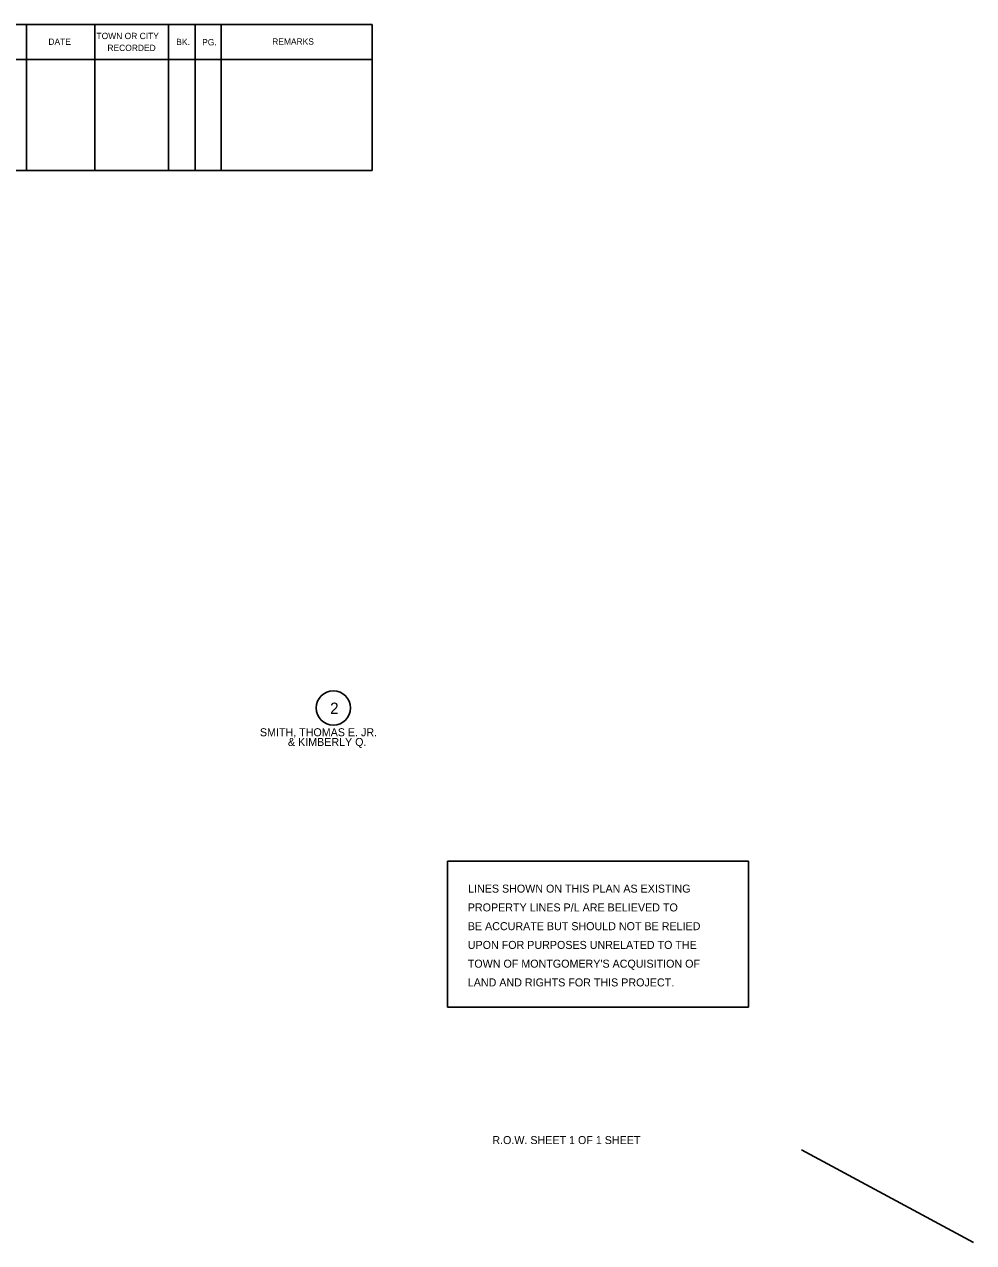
# Model space of a CAD drawing. Extents: x 10908 to 11683, y 59533 to 60252.
# Drawn here: x 11350.8 to 11682.8, y 59532.8 to 59959.1 of the extents above; entities that cross this region are included whole.
import ezdxf

# ---------------------------------------------------------------- set-up
doc = ezdxf.new("R2010")
doc.units = 0
for name, color, linetype in [('Level 1', 7, 'Continuous'), ('Level 4', 7, 'Continuous'), ('Level 5', 7, 'Continuous')]:
    doc.layers.add(name, color=color, linetype=linetype)

msp = doc.modelspace()

# ---------------------------------------------------------------- linework, layer by layer
at = {"layer": 'Level 1'}
for p, q in [((11047.77, 59959.1), (11472.37, 59959.1)), ((11351.56, 59959.01), (11351.56, 59907.92)), ((11375.36, 59907.92), (11375.36, 59959.1)), ((11401.19, 59907.92), (11401.19, 59958.93)), ((11410.46, 59907.92), (11410.46, 59959.1)), ((11419.55, 59907.92), (11419.55, 59959.1)), ((11472.37, 59959.1), (11472.37, 59907.92)), ((11047.77, 59946.84), (11472.37, 59946.84)), ((11047.77, 59907.92), (11472.37, 59907.92)), ((11498.77, 59666.27), (11604.06, 59666.27)), ((11498.77, 59666.27), (11498.78, 59615.28)), ((11604.06, 59666.27), (11604.06, 59615.28)), ((11498.78, 59615.28), (11604.06, 59615.28)), ((11622.59, 59565.36), (11682.76, 59532.84))]:
    msp.add_line(p, q, dxfattribs=at)
at = {"layer": 'Level 5'}
msp.add_circle((11458.84, 59719.92), 6, dxfattribs=at)

# ---------------------------------------------------------------- texts
at = {"layer": 'Level 1'}
for s, height, p in [('DATE', 2.207, (11359.17, 59951.94)), ('TOWN OR CITY', 2.2074, (11375.99, 59953.94)), ('BK.', 2.207, (11403.91, 59951.85)), ('PG.', 2.207, (11412.94, 59951.75)), ('REMARKS', 2.207, (11437.44, 59951.98)), ('RECORDED', 2.207, (11379.81, 59949.77)), ('LINES SHOWN ON THIS PLAN AS EXISTING', 2.8, (11505.95, 59655.31)), ('BE ACCURATE BUT SHOULD NOT BE RELIED', 2.8, (11505.85, 59642.17)), ('UPON FOR PURPOSES UNRELATED TO THE', 2.8, (11505.85, 59635.61)), ("TOWN OF MONTGOMERY'S ACQUISITION OF ", 2.8, (11505.85, 59629.05)), ('LAND AND RIGHTS FOR THIS PROJECT.', 2.8, (11505.85, 59622.49)), ('R.O.W. SHEET 1 OF 1 SHEET', 2.8, (11514.43, 59567.33))]:
    msp.add_text(s, height=height, dxfattribs=at).set_placement(p)
msp.add_text('PROPERTY LINES P/L ARE BELIEVED TO', height=2.8, rotation=0.0007, dxfattribs=at).set_placement((11505.85, 59648.73))
at = {"layer": 'Level 4'}
for s, p in [('SMITH, THOMAS E. JR.', (11433.14, 59710.02)), ('& KIMBERLY Q.', (11442.94, 59706.62))]:
    msp.add_text(s, height=2.8, dxfattribs=at).set_placement(p)
at = {"layer": 'Level 5'}
msp.add_text('2', height=4, dxfattribs=at).set_placement((11457.68, 59717.79))

doc.saveas('drawing.dxf')
